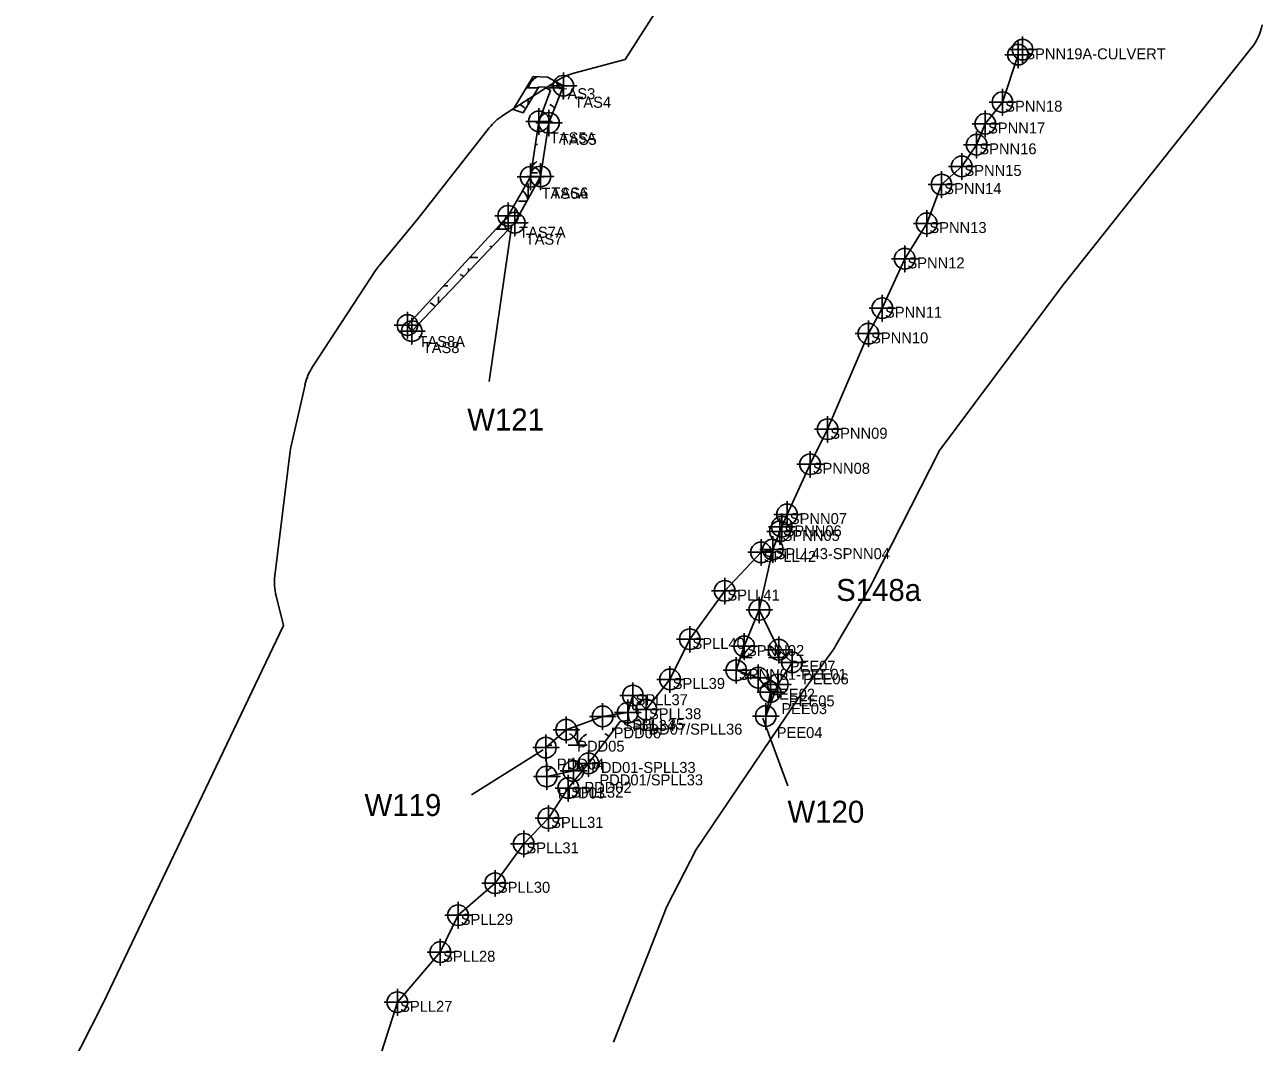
# Model space of a CAD drawing. Extents: x 1253697 to 1278588, y 912189 to 981699.
# Drawn here: x 1270988 to 1272115, y 978446 to 979373 of the extents above; entities that cross this region are included whole.
import ezdxf

# ---------------------------------------------------------------- set-up
doc = ezdxf.new("R2010")
doc.units = 0
for name, color, linetype in [('Default', 7, 'Continuous'), ('Exist Environmental Wetland Boundary', 7, 'Continuous'), ('Exist Environmental Wetland Boundary Cogo Comment', 7, 'Continuous'), ('Exist Environmental Wetland Boundary Cogo Number', 7, 'Continuous'), ('Exist Environmental Wetland Boundary Cogo Point CELL', 7, 'Continuous'), ('Exist Hydro Jurisdictional Stream or Body of Water Mitigable', 7, 'Continuous'), ('Exist Hydro Jurisdictional Stream or Body of Water Mitigable Cogo Comment', 7, 'Continuous'), ('Exist Hydro Jurisdictional Stream or Body of Water Mitigable Cogo Number', 7, 'Continuous'), ('Exist Hydro Jurisdictional Stream or Body of Water Mitigable Cogo Point CELL', 7, 'Continuous'), ('Exist Hydro Swamp or Marsh', 7, 'Continuous')]:
    doc.layers.add(name, color=color, linetype=linetype)

msp = doc.modelspace()

# ---------------------------------------------------------------- linework, layer by layer
at = {"layer": 'Default'}
for p, q in [((1271474.1, 979322.4), (1271423.4, 979290.1)), ((1271474.1, 979322.4), (1271423.4, 979290.1)), ((1271431.6, 979190.4), (1271410.8, 979047.7)), ((1271308.1, 979149.8), (1271250.1, 979061.1)), ((1271308.1, 979149.8), (1271250.1, 979061.1)), ((1271243.2, 979044.8), (1271230.5, 978989.4)), ((1271243.2, 979044.8), (1271230.5, 978989.4)), ((1271229.7, 978984.4), (1271215.7, 978870.9)), ((1271229.7, 978984.4), (1271215.7, 978870.9)), ((1271726.2, 978807), (1271758.6, 978862.5)), ((1271726.2, 978807), (1271758.6, 978862.5)), ((1271682.7, 978679.6), (1271660.1, 978741.3)), ((1271394.9, 978671.4), (1271460, 978712.5))]:
    msp.add_line(p, q, dxfattribs=at)
for points in [[(1271671.1, 979554.4), (1271534.8, 979341), (1271488, 979328.5)], [(1271671.1, 979554.4), (1271534.8, 979341), (1271488, 979328.5)], [(1271760, 978865), (1271820.9, 978985), (1271933.6, 979135.9), (1272104.9, 979351.5)], [(1271760, 978865), (1271820.9, 978985), (1271933.6, 979135.9), (1272104.9, 979351.5)], [(1271410.9, 979278.7), (1271345.9, 979195.8), (1271311.5, 979154.3)], [(1271410.9, 979278.7), (1271345.9, 979195.8), (1271311.5, 979154.3)], [(1271216.8, 978852.7), (1271223.5, 978825.8), (1271059.3, 978481.8), (1270988, 978341.3)], [(1271216.8, 978852.7), (1271223.5, 978825.8), (1271059.3, 978481.8), (1270988, 978341.3)], [(1271524.1, 978446.2), (1271572.5, 978569.8), (1271599.3, 978621.7), (1271696.6, 978765.9), (1271723.4, 978802.6)], [(1271524.1, 978446.2), (1271572.5, 978569.8), (1271599.3, 978621.7), (1271696.6, 978765.9), (1271723.4, 978802.6)]]:
    msp.add_lwpolyline(points, dxfattribs=at)
for centre, start, end in [((1272065.7, 979382.6), 321.5427, 348.5477), ((1272065.7, 979382.6), 321.5427, 348.5477), ((1271500.9, 979280.2), 104.9596, 122.5214), ((1271500.9, 979280.2), 104.9596, 122.5214), ((1271450.3, 979247.9), 122.5214, 141.9041), ((1271450.3, 979247.9), 122.5214, 141.9041), ((1271350, 979122.4), 140.31, 146.8073), ((1271350, 979122.4), 140.31, 146.8073), ((1271291.9, 979033.7), 146.8073, 167.1402), ((1271291.9, 979033.7), 146.8073, 167.1402), ((1271279.3, 978978.3), 167.1402, 172.9873), ((1271279.3, 978978.3), 167.1402, 172.9873), ((1271265.3, 978864.8), 172.9873, 194.0138), ((1271265.3, 978864.8), 172.9873, 194.0138), ((1271715.4, 978887.7), 329.772, 333.0773), ((1271715.4, 978887.7), 329.772, 333.0773), ((1271683, 978832.1), 323.8247, 329.772), ((1271683, 978832.1), 323.8247, 329.772)]:
    msp.add_arc(centre, 50, start, end, dxfattribs=at)
at = {"layer": 'Exist Environmental Wetland Boundary'}
for p, q in [((1271464.9, 979289.5), (1271467.7, 979289.5)), ((1271453, 979263.7), (1271454.9, 979263.7)), ((1271449.1, 979237.9), (1271454.9, 979237.9)), ((1271437.7, 979212.1), (1271445.2, 979212.1)), ((1271393, 979160.6), (1271400.5, 979160.6)), ((1271369.3, 979134.8), (1271373.3, 979134.8)), ((1271345.6, 979109), (1271346.1, 979109))]:
    msp.add_line(p, q, dxfattribs=at)
msp.add_lwpolyline([(1271450.9, 979325.6), (1271464, 979324.9), (1271478.4, 979317.1), (1271465.3, 979283.3), (1271457.6, 979234.5), (1271434.1, 979192.4), (1271340.4, 979093.7), (1271336.5, 979099.2), (1271428.1, 979198.7), (1271448.5, 979234.2), (1271456.1, 979284.7), (1271466.8, 979312.8), (1271461.4, 979315.7), (1271456, 979316), (1271441.8, 979292.6), (1271432.7, 979295.5)], close=True, dxfattribs=at)
for points in [[(1271444.7, 979315.3), (1271446.3, 979315.3), (1271446.3, 979317.9)], [(1271446.3, 979317.9), (1271446.3, 979315.3), (1271454.9, 979315.3)], [(1271464.9, 979315.3), (1271473.5, 979315.3), (1271473.5, 979319.7)], [(1271473.5, 979319.7), (1271473.5, 979315.3), (1271477.7, 979315.3)], [(1271446.3, 979300), (1271446.3, 979305.3), (1271446.3, 979300)], [(1271473.5, 979304.5), (1271473.5, 979305.3), (1271473.5, 979304.5)], [(1271446.3, 979214.2), (1271446.3, 979227.9), (1271446.3, 979214.2)], [(1271416.8, 979186.4), (1271419.1, 979186.4), (1271419.1, 979188.9)], [(1271419.1, 979188.9), (1271419.1, 979186.4), (1271427.7, 979186.4)], [(1271391.9, 979147.9), (1271391.9, 979150.6), (1271391.9, 979147.9)], [(1271364.7, 979119.3), (1271364.7, 979124.8), (1271364.7, 979119.3)], [(1271337.5, 979097.9), (1271337.5, 979099), (1271337.5, 979097.9)], [(1271635.8, 978784.9), (1271655.9, 978778.1), (1271666.9, 978765), (1271662.7, 978743.2), (1271673.7, 978772), (1271686.6, 978792.1), (1271674.5, 978803.6), (1271656.8, 978839.9)], [(1271501.2, 978700.1), (1271487.5, 978693.2), (1271463.3, 978688.2), (1271462.5, 978714.5), (1271481, 978730.8), (1271514.2, 978742.9), (1271537, 978746.3)]]:
    msp.add_lwpolyline(points, dxfattribs=at)
for centre, radius, start, end in [((1271434.1, 979314.4), 12.3, 4.1403, 14.1388), ((1271464.6, 979309.2), 19.2, 122.6084, 161.6222), ((1271461.3, 979314.4), 12.3, 4.1403, 30.5007), ((1271491.8, 979309.2), 19.2, 149.9516, 161.6222), ((1271434.1, 979288.6), 12.3, 36.9332, 67.535), ((1271461.3, 979288.6), 12.3, 41.2841, 67.535), ((1271464.6, 979231.9), 19.2, 122.1274, 138.9295), ((1271434.1, 979211.3), 12.3, 11.8555, 54.916), ((1271437.4, 979180.3), 19.2, 122.1274, 161.6222), ((1271406.9, 979185.5), 12.3, 4.1403, 14.4216), ((1271406.9, 979159.7), 12.3, 59.261, 67.535), ((1271379.7, 979133.9), 12.3, 50.0058, 67.535), ((1271352.4, 979108.1), 12.3, 40.8431, 67.535)]:
    msp.add_arc(centre, radius, start, end, dxfattribs=at)
at = {"layer": 'Exist Environmental Wetland Boundary Cogo Point CELL'}
for points in [[(1271478.4, 979329.1), (1271478.4, 979305.1), (1271478.4, 979317.1), (1271490.4, 979317.1), (1271466.4, 979317.1)], [(1271456.1, 979296.7), (1271456.1, 979272.7), (1271456.1, 979284.7), (1271468.1, 979284.7), (1271444.1, 979284.7)], [(1271465.3, 979295.3), (1271465.3, 979271.3), (1271465.3, 979283.3), (1271477.3, 979283.3), (1271453.3, 979283.3)], [(1271448.5, 979246.2), (1271448.5, 979222.2), (1271448.5, 979234.2), (1271460.5, 979234.2), (1271436.5, 979234.2)], [(1271457.6, 979246.5), (1271457.6, 979222.5), (1271457.6, 979234.5), (1271469.6, 979234.5), (1271445.6, 979234.5)], [(1271428.1, 979210.7), (1271428.1, 979186.7), (1271428.1, 979198.7), (1271440.1, 979198.7), (1271416.1, 979198.7)], [(1271434.1, 979204.4), (1271434.1, 979180.4), (1271434.1, 979192.4), (1271446.1, 979192.4), (1271422.1, 979192.4)], [(1271336.5, 979111.2), (1271336.5, 979087.2), (1271336.5, 979099.2), (1271348.5, 979099.2), (1271324.5, 979099.2)], [(1271340.4, 979105.7), (1271340.4, 979081.7), (1271340.4, 979093.7), (1271352.4, 979093.7), (1271328.4, 979093.7)], [(1271674.5, 978815.6), (1271674.5, 978791.6), (1271674.5, 978803.6), (1271686.5, 978803.6), (1271662.5, 978803.6)], [(1271686.6, 978804.1), (1271686.6, 978780.1), (1271686.6, 978792.1), (1271698.6, 978792.1), (1271674.6, 978792.1)], [(1271655.9, 978790.1), (1271655.9, 978766.1), (1271655.9, 978778.1), (1271667.9, 978778.1), (1271643.9, 978778.1)], [(1271666.9, 978777), (1271666.9, 978753), (1271666.9, 978765), (1271678.9, 978765), (1271654.9, 978765)], [(1271673.7, 978784), (1271673.7, 978760), (1271673.7, 978772), (1271685.7, 978772), (1271661.7, 978772)], [(1271514.2, 978754.9), (1271514.2, 978730.9), (1271514.2, 978742.9), (1271526.2, 978742.9), (1271502.2, 978742.9)], [(1271537, 978758.3), (1271537, 978734.3), (1271537, 978746.3), (1271549, 978746.3), (1271525, 978746.3)], [(1271662.7, 978755.2), (1271662.7, 978731.2), (1271662.7, 978743.2), (1271674.7, 978743.2), (1271650.7, 978743.2)], [(1271481, 978742.8), (1271481, 978718.8), (1271481, 978730.8), (1271493, 978730.8), (1271469, 978730.8)], [(1271462.5, 978726.5), (1271462.5, 978702.5), (1271462.5, 978714.5), (1271474.5, 978714.5), (1271450.5, 978714.5)], [(1271501.2, 978712.1), (1271501.2, 978688.1), (1271501.2, 978700.1), (1271513.2, 978700.1), (1271489.2, 978700.1)], [(1271463.3, 978700.2), (1271463.3, 978676.2), (1271463.3, 978688.2), (1271475.3, 978688.2), (1271451.3, 978688.2)], [(1271487.5, 978705.2), (1271487.5, 978681.2), (1271487.5, 978693.2), (1271499.5, 978693.2), (1271475.5, 978693.2)]]:
    msp.add_lwpolyline(points, dxfattribs=at)
for centre in [(1271478.4, 979317.1), (1271456.1, 979284.7), (1271465.3, 979283.3), (1271448.5, 979234.2), (1271457.6, 979234.5), (1271428.1, 979198.7), (1271434.1, 979192.4), (1271336.5, 979099.2), (1271340.4, 979093.7), (1271674.5, 978803.6), (1271686.6, 978792.1), (1271655.9, 978778.1), (1271673.7, 978772), (1271666.9, 978765), (1271537, 978746.3), (1271514.2, 978742.9), (1271662.7, 978743.2), (1271481, 978730.8), (1271462.5, 978714.5), (1271501.2, 978700.1), (1271463.3, 978688.2), (1271487.5, 978693.2)]:
    msp.add_circle(centre, 9.38, dxfattribs=at)
at = {"layer": 'Exist Hydro Jurisdictional Stream or Body of Water Mitigable'}
for points in [[(1271635.8, 978784.9), (1271643.1, 978806.7), (1271656.8, 978839.9), (1271669.2, 978894.8), (1271675.6, 978911.4), (1271677.3, 978915.6), (1271682.1, 978926.8), (1271703, 978972.5), (1271719, 979004.4), (1271756.1, 979091.4), (1271768.8, 979114.6), (1271789.2, 979159.6), (1271809.2, 979191.8), (1271822.7, 979227.2), (1271841.1, 979243.7), (1271854.7, 979263.4), (1271862.6, 979282.5), (1271878.2, 979302.2), (1271892.4, 979345.4)], [(1271310.4, 978429.5), (1271327.3, 978482.7), (1271366.4, 978528.3), (1271382.5, 978561.9), (1271416.3, 978591), (1271442.3, 978626.9), (1271464.8, 978650.2), (1271482.9, 978677.7), (1271501.2, 978700.1), (1271530, 978738.4), (1271538.2, 978739.5), (1271537, 978746.3), (1271541.7, 978761.9), (1271553.9, 978749.1), (1271575.5, 978776.6), (1271593.5, 978813.2), (1271625.3, 978857.2), (1271658.4, 978892.3), (1271669.2, 978894.9)]]:
    msp.add_lwpolyline(points, dxfattribs=at)
at = {"layer": 'Exist Hydro Jurisdictional Stream or Body of Water Mitigable Cogo Point CELL'}
for points in [[(1271896.5, 979362), (1271896.5, 979338), (1271896.5, 979350), (1271908.5, 979350), (1271884.5, 979350)], [(1271892.4, 979357.4), (1271892.4, 979333.4), (1271892.4, 979345.4), (1271904.4, 979345.4), (1271880.4, 979345.4)], [(1271878.2, 979314.2), (1271878.2, 979290.2), (1271878.2, 979302.2), (1271890.2, 979302.2), (1271866.2, 979302.2)], [(1271862.6, 979294.5), (1271862.6, 979270.5), (1271862.6, 979282.5), (1271874.6, 979282.5), (1271850.6, 979282.5)], [(1271854.7, 979275.4), (1271854.7, 979251.4), (1271854.7, 979263.4), (1271866.7, 979263.4), (1271842.7, 979263.4)], [(1271841.1, 979255.7), (1271841.1, 979231.7), (1271841.1, 979243.7), (1271853.1, 979243.7), (1271829.1, 979243.7)], [(1271822.7, 979239.2), (1271822.7, 979215.2), (1271822.7, 979227.2), (1271834.7, 979227.2), (1271810.7, 979227.2)], [(1271809.2, 979203.8), (1271809.2, 979179.8), (1271809.2, 979191.8), (1271821.2, 979191.8), (1271797.2, 979191.8)], [(1271789.2, 979171.6), (1271789.2, 979147.6), (1271789.2, 979159.6), (1271801.2, 979159.6), (1271777.2, 979159.6)], [(1271768.8, 979126.6), (1271768.8, 979102.6), (1271768.8, 979114.6), (1271780.8, 979114.6), (1271756.8, 979114.6)], [(1271756.1, 979103.4), (1271756.1, 979079.4), (1271756.1, 979091.4), (1271768.1, 979091.4), (1271744.1, 979091.4)], [(1271719, 979016.4), (1271719, 978992.4), (1271719, 979004.4), (1271731, 979004.4), (1271707, 979004.4)], [(1271703, 978984.5), (1271703, 978960.5), (1271703, 978972.5), (1271715, 978972.5), (1271691, 978972.5)], [(1271682.1, 978938.8), (1271682.1, 978914.8), (1271682.1, 978926.8), (1271694.1, 978926.8), (1271670.1, 978926.8)], [(1271675.6, 978923.4), (1271675.6, 978899.4), (1271675.6, 978911.4), (1271687.6, 978911.4), (1271663.6, 978911.4)], [(1271677.3, 978927.6), (1271677.3, 978903.6), (1271677.3, 978915.6), (1271689.3, 978915.6), (1271665.3, 978915.6)], [(1271658.4, 978904.3), (1271658.4, 978880.3), (1271658.4, 978892.3), (1271670.4, 978892.3), (1271646.4, 978892.3)], [(1271669.2, 978906.9), (1271669.2, 978882.9), (1271669.2, 978894.9), (1271681.2, 978894.9), (1271657.2, 978894.9)], [(1271625.3, 978869.2), (1271625.3, 978845.2), (1271625.3, 978857.2), (1271637.3, 978857.2), (1271613.3, 978857.2)], [(1271656.8, 978851.9), (1271656.8, 978827.9), (1271656.8, 978839.9), (1271668.8, 978839.9), (1271644.8, 978839.9)], [(1271593.5, 978825.2), (1271593.5, 978801.2), (1271593.5, 978813.2), (1271605.5, 978813.2), (1271581.5, 978813.2)], [(1271643.1, 978818.7), (1271643.1, 978794.7), (1271643.1, 978806.7), (1271655.1, 978806.7), (1271631.1, 978806.7)], [(1271575.5, 978788.6), (1271575.5, 978764.6), (1271575.5, 978776.6), (1271587.5, 978776.6), (1271563.5, 978776.6)], [(1271635.8, 978796.9), (1271635.8, 978772.9), (1271635.8, 978784.9), (1271647.8, 978784.9), (1271623.8, 978784.9)], [(1271541.7, 978773.9), (1271541.7, 978749.9), (1271541.7, 978761.9), (1271553.7, 978761.9), (1271529.7, 978761.9)], [(1271553.9, 978761.1), (1271553.9, 978737.1), (1271553.9, 978749.1), (1271565.9, 978749.1), (1271541.9, 978749.1)], [(1271482.9, 978689.7), (1271482.9, 978665.7), (1271482.9, 978677.7), (1271494.9, 978677.7), (1271470.9, 978677.7)], [(1271464.8, 978662.2), (1271464.8, 978638.2), (1271464.8, 978650.2), (1271476.8, 978650.2), (1271452.8, 978650.2)], [(1271442.3, 978638.9), (1271442.3, 978614.9), (1271442.3, 978626.9), (1271454.3, 978626.9), (1271430.3, 978626.9)], [(1271416.3, 978603), (1271416.3, 978579), (1271416.3, 978591), (1271428.3, 978591), (1271404.3, 978591)], [(1271382.5, 978573.9), (1271382.5, 978549.9), (1271382.5, 978561.9), (1271394.5, 978561.9), (1271370.5, 978561.9)], [(1271366.4, 978540.3), (1271366.4, 978516.3), (1271366.4, 978528.3), (1271378.4, 978528.3), (1271354.4, 978528.3)], [(1271327.3, 978494.7), (1271327.3, 978470.7), (1271327.3, 978482.7), (1271339.3, 978482.7), (1271315.3, 978482.7)]]:
    msp.add_lwpolyline(points, dxfattribs=at)
for centre in [(1271892.4, 979345.4), (1271896.5, 979350), (1271878.2, 979302.2), (1271862.6, 979282.5), (1271854.7, 979263.4), (1271841.1, 979243.7), (1271822.7, 979227.2), (1271809.2, 979191.8), (1271789.2, 979159.6), (1271768.8, 979114.6), (1271756.1, 979091.4), (1271719, 979004.4), (1271703, 978972.5), (1271682.1, 978926.8), (1271677.3, 978915.6), (1271675.6, 978911.4), (1271658.4, 978892.3), (1271669.2, 978894.9), (1271625.3, 978857.2), (1271656.8, 978839.9), (1271593.5, 978813.2), (1271643.1, 978806.7), (1271635.8, 978784.9), (1271575.5, 978776.6), (1271541.7, 978761.9), (1271553.9, 978749.1), (1271482.9, 978677.7), (1271464.8, 978650.2), (1271442.3, 978626.9), (1271416.3, 978591), (1271382.5, 978561.9), (1271366.4, 978528.3), (1271327.3, 978482.7)]:
    msp.add_circle(centre, 9.38, dxfattribs=at)
at = {"layer": 'Exist Hydro Swamp or Marsh'}
for p, q in [((1271666.2, 978765.8), (1271671.4, 978765.8)), ((1271464.9, 978716.6), (1271467.8, 978716.6))]:
    msp.add_line(p, q, dxfattribs=at)
for points in [[(1271639.7, 978796.6), (1271641.7, 978796.6), (1271641.7, 978802.5)], [(1271641.7, 978802.5), (1271641.7, 978796.6), (1271650.3, 978796.6)], [(1271665.3, 978796.6), (1271673.9, 978796.6), (1271673.9, 978804.8)], [(1271673.9, 978804.8), (1271673.9, 978796.6), (1271681.9, 978796.6)], [(1271673.9, 978772.3), (1271673.9, 978781.6), (1271673.9, 978772.3)], [(1271482.8, 978716.6), (1271491.4, 978716.6), (1271491.4, 978732.4), (1271491.4, 978716.6), (1271500, 978716.6)], [(1271523.6, 978729.9), (1271523.6, 978732.4), (1271523.6, 978729.9)], [(1271491.4, 978695.2), (1271491.4, 978701.6), (1271491.4, 978695.2)]]:
    msp.add_lwpolyline(points, dxfattribs=at)
for centre, radius, start, end in [((1271629.4, 978795.7), 12.3, 4.1403, 21.1797), ((1271659.9, 978790.5), 19.2, 122.1274, 161.6222), ((1271661.6, 978795.7), 12.3, 4.1403, 67.535), ((1271692.1, 978790.5), 19.2, 144.5677, 161.6222), ((1271661.6, 978764.9), 12.3, 23.5718, 67.535), ((1271479.2, 978715.7), 12.3, 4.1403, 67.535), ((1271509.7, 978710.6), 19.2, 122.1274, 161.6222), ((1271511.4, 978715.7), 12.3, 47.0251, 67.535), ((1271477.5, 978679.8), 19.2, 122.1274, 138.1661), ((1271479.2, 978685), 12.3, 43.7188, 67.535)]:
    msp.add_arc(centre, radius, start, end, dxfattribs=at)

# ---------------------------------------------------------------- texts
at = {"layer": 'Exist Environmental Wetland Boundary Cogo Comment'}
for s, p in [('TAS3', (1271474, 979304.9)), ('TAS4', (1271488.4, 979297.1)), ('TAS5A', (1271466.1, 979264.7)), ('TAS5', (1271475.3, 979263.3)), ('TAS6A', (1271458.5, 979214.2)), ('TAS6', (1271467.6, 979214.5)), ('TAS7A', (1271438.1, 979178.7)), ('TAS7', (1271444.1, 979172.4)), ('TAS8A', (1271346.5, 979079.2)), ('TAS8', (1271350.4, 979073.7)), ('PEE07', (1271684.5, 978783.6)), ('PEE06', (1271696.6, 978772.1)), ('PEE02', (1271665.9, 978758.1)), ('PEE03', (1271676.9, 978745)), ('PEE05', (1271683.7, 978752)), ('PDD06', (1271524.2, 978722.9)), ('PDD07/SPLL36', (1271547, 978726.3)), ('PEE04', (1271672.7, 978723.2)), ('PDD05', (1271491, 978710.8)), ('PDD04', (1271472.5, 978694.5)), ('PDD01/SPLL33', (1271511.2, 978680.1)), ('PDD03', (1271473.3, 978668.2)), ('PDD02', (1271497.5, 978673.2))]:
    msp.add_text(s, height=10, dxfattribs=at).set_placement(p)
at = {"layer": 'Exist Environmental Wetland Boundary Cogo Number'}
for s, p in [('W121', (1271390.9, 979003.2)), ('W119', (1271297.4, 978652.2)), ('W120', (1271682.5, 978646.1))]:
    msp.add_text(s, height=20, dxfattribs=at).set_placement(p)
at = {"layer": 'Exist Hydro Jurisdictional Stream or Body of Water Mitigable Cogo Comment'}
for s, p in [('SPNN19A-CULVERT', (1271899, 979341.2)), ('SPNN18', (1271880.7, 979293.5)), ('SPNN17', (1271865.1, 979273.7)), ('SPNN16', (1271857.2, 979254.7)), ('SPNN15', (1271843.6, 979235)), ('SPNN14', (1271825.2, 979218.5)), ('SPNN13', (1271811.7, 979183)), ('SPNN12', (1271791.7, 979150.8)), ('SPNN11', (1271771.3, 979105.9)), ('SPNN10', (1271758.6, 979082.6)), ('SPNN09', (1271721.5, 978995.7)), ('SPNN08', (1271705.5, 978963.8)), ('SPNN07', (1271684.6, 978918)), ('SPNN05', (1271678.1, 978902.7)), ('SPNN06', (1271679.8, 978906.8)), ('SPLL42', (1271660.9, 978883.5)), ('SPLL43-SPNN04', (1271671.7, 978886.1)), ('SPLL41', (1271627.8, 978848.4)), ('SPLL40', (1271596, 978804.4)), ('SPNN02', (1271645.6, 978797.9)), ('SPLL39', (1271578, 978767.9)), ('SPNN01-PEE01', (1271638.3, 978776.2)), ('SPLL37', (1271544.2, 978753.1)), ('SPLL38', (1271556.4, 978740.3)), ('SPLL34', (1271532.5, 978729.6)), ('SPLL35', (1271540.7, 978730.8)), ('PDD01-SPLL33', (1271503.7, 978691.4)), ('SPLL32', (1271485.4, 978668.9)), ('SPLL31', (1271467.3, 978641.4)), ('SPLL31', (1271444.8, 978618.2)), ('SPLL30', (1271418.8, 978582.3)), ('SPLL29', (1271385, 978553.1)), ('SPLL28', (1271368.9, 978519.5)), ('SPLL27', (1271329.8, 978473.9))]:
    msp.add_text(s, height=10, dxfattribs=at).set_placement(p)
at = {"layer": 'Exist Hydro Jurisdictional Stream or Body of Water Mitigable Cogo Number'}
msp.add_text('S148a', height=20, dxfattribs=at).set_placement((1271726.8, 978848))

doc.saveas('drawing.dxf')
